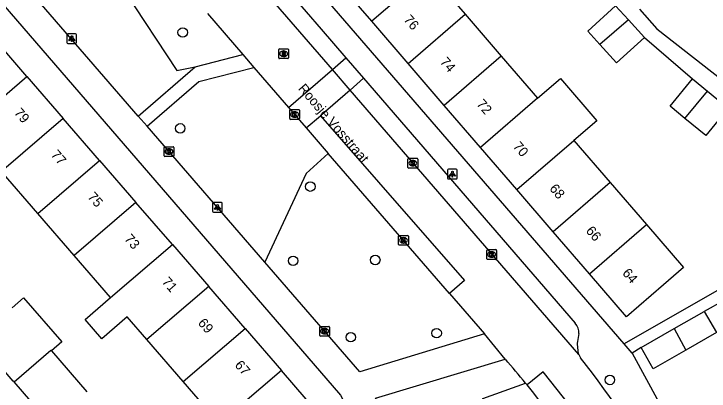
# Model space of a CAD drawing. Extents: x 160304 to 160954, y 383686 to 384161.
# Drawn here: x 160603.5 to 160674.9, y 383939.6 to 383978.2 of the extents above; entities that cross this region are included whole.
import ezdxf

# ---------------------------------------------------------------- set-up
doc = ezdxf.new("R2010")
doc.units = 0
for name, color, linetype in [('IMGEO_Boom', 7, 'Continuous'), ('IMGEO_Groenvoorziening', 7, 'Continuous'), ('IMGEO_Kolk', 7, 'Continuous'), ('IMGEO_Lichtpunt', 7, 'Continuous'), ('IMGEO_Openbare_ruimte_label', 7, 'Continuous'), ('IMGEO_Pand', 7, 'Continuous'), ('IMGEO_Pand_nummerreeks', 7, 'Continuous'), ('IMGEO_Parkeervlak_open', 7, 'Continuous'), ('IMGEO_Rijbaan_lokaal_open', 7, 'Continuous'), ('IMGEO_Rioolput', 7, 'Continuous'), ('IMGEO_Voetpad_open', 7, 'Continuous')]:
    doc.layers.add(name, color=color, linetype=linetype)

msp = doc.modelspace()

# ---------------------------------------------------------------- linework, layer by layer
at = {"layer": 'IMGEO_Boom'}
for centre in [(160620.841, 383976.338), (160620.586, 383966.501), (160633.933, 383960.53), (160632.169, 383952.919), (160640.598, 383953.001), (160646.895, 383945.495), (160638.087, 383945.081), (160664.674, 383940.697)]:
    msp.add_circle(centre, 0.489, dxfattribs=at)
at = {"layer": 'IMGEO_Groenvoorziening'}
for points in [[(160613.422, 383989.772), (160610.309, 383986.182), (160614.865, 383980.618), (160620.248, 383972.445), (160622.102, 383972.826)], [(160635.78, 383963.935), (160633.522, 383961.858), (160629.26, 383952.781)], [(160667.2, 383923.012), (160658.953, 383920.96), (160657.989, 383920.86), (160657.227, 383921.053), (160656.563, 383921.472), (160656.06, 383922.076), (160650.385, 383929.86), (160651.645, 383938.783), (160656.021, 383940.378)]]:
    msp.add_lwpolyline(points, dxfattribs=at)
at = {"layer": 'IMGEO_Kolk'}
for p, q in [((160631.822, 383967.502), (160631.822, 383968.354)), ((160631.897, 383968.428), (160632.749, 383968.428)), ((160632.31, 383968.208), (160632.335, 383968.208)), ((160632.823, 383968.354), (160632.823, 383967.502)), ((160632.749, 383967.428), (160631.897, 383967.428)), ((160632.333, 383967.648), (160632.308, 383967.648)), ((160618.929, 383963.696), (160618.929, 383964.548)), ((160619.004, 383964.622), (160619.856, 383964.622)), ((160619.93, 383964.548), (160619.93, 383963.696)), ((160619.44, 383963.842), (160619.415, 383963.842)), ((160619.417, 383964.402), (160619.442, 383964.402)), ((160619.856, 383963.622), (160619.004, 383963.622)), ((160643.955, 383962.505), (160643.955, 383963.357)), ((160644.03, 383963.431), (160644.882, 383963.431)), ((160644.443, 383963.211), (160644.468, 383963.211)), ((160644.956, 383963.357), (160644.956, 383962.505)), ((160644.882, 383962.431), (160644.03, 383962.431)), ((160644.466, 383962.651), (160644.441, 383962.651)), ((160642.993, 383954.592), (160642.993, 383955.444)), ((160643.068, 383955.518), (160643.92, 383955.518)), ((160643.481, 383955.298), (160643.506, 383955.298)), ((160643.994, 383955.444), (160643.994, 383954.592)), ((160643.92, 383954.518), (160643.068, 383954.518)), ((160643.504, 383954.738), (160643.479, 383954.738)), ((160652.044, 383953.135), (160652.044, 383953.987)), ((160652.119, 383954.061), (160652.971, 383954.061)), ((160652.532, 383953.841), (160652.557, 383953.841)), ((160653.045, 383953.987), (160653.045, 383953.135)), ((160652.971, 383953.061), (160652.119, 383953.061)), ((160652.555, 383953.281), (160652.53, 383953.281)), ((160634.904, 383945.265), (160634.904, 383946.117)), ((160634.979, 383946.191), (160635.831, 383946.191)), ((160635.392, 383945.971), (160635.417, 383945.971)), ((160635.905, 383946.117), (160635.905, 383945.265)), ((160635.831, 383945.191), (160634.979, 383945.191)), ((160635.415, 383945.411), (160635.39, 383945.411))]:
    msp.add_line(p, q, dxfattribs=at)
for points in [[(160631.822, 383967.502), (160631.822, 383968.354)], [(160631.897, 383968.428), (160632.749, 383968.428)], [(160632.143, 383968.128), (160632.266, 383968.128), (160632.266, 383967.977), (160632.396, 383968.128), (160632.56, 383968.128), (160632.414, 383967.977), (160632.567, 383967.728), (160632.415, 383967.728), (160632.33, 383967.892), (160632.266, 383967.825), (160632.266, 383967.728), (160632.143, 383967.728), (160632.143, 383968.128)], [(160632.823, 383968.354), (160632.823, 383967.502)], [(160632.749, 383967.428), (160631.897, 383967.428)], [(160618.929, 383963.696), (160618.929, 383964.548)], [(160619.004, 383964.622), (160619.856, 383964.622)], [(160619.93, 383964.548), (160619.93, 383963.696)], [(160619.25, 383964.322), (160619.373, 383964.322), (160619.373, 383964.171), (160619.503, 383964.322), (160619.667, 383964.322), (160619.521, 383964.171), (160619.674, 383963.922), (160619.522, 383963.922), (160619.437, 383964.086), (160619.373, 383964.019), (160619.373, 383963.922), (160619.25, 383963.922), (160619.25, 383964.322)], [(160619.856, 383963.622), (160619.004, 383963.622)], [(160643.955, 383962.505), (160643.955, 383963.357)], [(160644.03, 383963.431), (160644.882, 383963.431)], [(160644.276, 383963.131), (160644.399, 383963.131), (160644.399, 383962.98), (160644.529, 383963.131), (160644.693, 383963.131), (160644.547, 383962.98), (160644.7, 383962.731), (160644.548, 383962.731), (160644.463, 383962.895), (160644.399, 383962.828), (160644.399, 383962.731), (160644.276, 383962.731), (160644.276, 383963.131)], [(160644.956, 383963.357), (160644.956, 383962.505)], [(160644.882, 383962.431), (160644.03, 383962.431)], [(160642.993, 383954.592), (160642.993, 383955.444)], [(160643.068, 383955.518), (160643.92, 383955.518)], [(160643.314, 383955.218), (160643.437, 383955.218), (160643.437, 383955.067), (160643.567, 383955.218), (160643.731, 383955.218), (160643.585, 383955.067), (160643.738, 383954.818), (160643.586, 383954.818), (160643.501, 383954.982), (160643.437, 383954.915), (160643.437, 383954.818), (160643.314, 383954.818), (160643.314, 383955.218)], [(160643.994, 383955.444), (160643.994, 383954.592)], [(160643.92, 383954.518), (160643.068, 383954.518)], [(160652.044, 383953.135), (160652.044, 383953.987)], [(160652.119, 383954.061), (160652.971, 383954.061)], [(160652.365, 383953.761), (160652.488, 383953.761), (160652.488, 383953.61), (160652.618, 383953.761), (160652.782, 383953.761), (160652.636, 383953.61), (160652.789, 383953.361), (160652.637, 383953.361), (160652.552, 383953.525), (160652.488, 383953.458), (160652.488, 383953.361), (160652.365, 383953.361), (160652.365, 383953.761)], [(160653.045, 383953.987), (160653.045, 383953.135)], [(160652.971, 383953.061), (160652.119, 383953.061)], [(160634.904, 383945.265), (160634.904, 383946.117)], [(160634.979, 383946.191), (160635.831, 383946.191)], [(160635.225, 383945.891), (160635.348, 383945.891), (160635.348, 383945.74), (160635.478, 383945.891), (160635.642, 383945.891), (160635.496, 383945.74), (160635.649, 383945.491), (160635.497, 383945.491), (160635.412, 383945.655), (160635.348, 383945.588), (160635.348, 383945.491), (160635.225, 383945.491), (160635.225, 383945.891)], [(160635.905, 383946.117), (160635.905, 383945.265)], [(160635.831, 383945.191), (160634.979, 383945.191)]]:
    msp.add_lwpolyline(points, dxfattribs=at)
for centre, start, end in [((160631.899, 383968.352), 91.55205, 178.44795), ((160631.899, 383968.352), 91.55205, 178.44795), ((160632.747, 383968.352), 1.55205, 88.44795), ((160632.747, 383968.352), 1.55205, 88.44795), ((160631.899, 383967.504), 181.55205, 268.44795), ((160631.899, 383967.504), 181.55205, 268.44795), ((160632.747, 383967.504), 271.55205, 358.44795), ((160632.747, 383967.504), 271.55205, 358.44795), ((160619.006, 383964.546), 91.55205, 178.44795), ((160619.006, 383964.546), 91.55205, 178.44795), ((160619.854, 383964.546), 1.55205, 88.44795), ((160619.854, 383964.546), 1.55205, 88.44795), ((160619.006, 383963.698), 181.55205, 268.44795), ((160619.006, 383963.698), 181.55205, 268.44795), ((160619.854, 383963.698), 271.55205, 358.44795), ((160619.854, 383963.698), 271.55205, 358.44795), ((160644.032, 383963.355), 91.55205, 178.44795), ((160644.032, 383963.355), 91.55205, 178.44795), ((160644.88, 383963.355), 1.55205, 88.44795), ((160644.88, 383963.355), 1.55205, 88.44795), ((160644.032, 383962.507), 181.55205, 268.44795), ((160644.032, 383962.507), 181.55205, 268.44795), ((160644.88, 383962.507), 271.55205, 358.44795), ((160644.88, 383962.507), 271.55205, 358.44795), ((160643.07, 383955.442), 91.55205, 178.44795), ((160643.07, 383955.442), 91.55205, 178.44795), ((160643.918, 383955.442), 1.55205, 88.44795), ((160643.918, 383955.442), 1.55205, 88.44795), ((160643.07, 383954.594), 181.55205, 268.44795), ((160643.07, 383954.594), 181.55205, 268.44795), ((160643.918, 383954.594), 271.55205, 358.44795), ((160643.918, 383954.594), 271.55205, 358.44795), ((160652.121, 383953.985), 91.55205, 178.44795), ((160652.121, 383953.985), 91.55205, 178.44795), ((160652.969, 383953.985), 1.55205, 88.44795), ((160652.969, 383953.985), 1.55205, 88.44795), ((160652.121, 383953.137), 181.55205, 268.44795), ((160652.121, 383953.137), 181.55205, 268.44795), ((160652.969, 383953.137), 271.55205, 358.44795), ((160652.969, 383953.137), 271.55205, 358.44795), ((160634.981, 383946.115), 91.55205, 178.44795), ((160634.981, 383946.115), 91.55205, 178.44795), ((160635.829, 383946.115), 1.55205, 88.44795), ((160635.829, 383946.115), 1.55205, 88.44795), ((160634.981, 383945.267), 181.55205, 268.44795), ((160634.981, 383945.267), 181.55205, 268.44795), ((160635.829, 383945.267), 271.55205, 358.44795), ((160635.829, 383945.267), 271.55205, 358.44795)]:
    msp.add_arc(centre, 0.0765, start, end, dxfattribs=at)
for centre, major_axis, ratio, start_param, end_param in [((160632.309, 383967.928), (-0.387, 0.002), 0.722429, 4.712389, 7.853982), ((160632.334, 383967.928), (-0.39, 0.002), 0.717154, 1.570796, 4.712389), ((160619.416, 383964.122), (-0.387, 0.002), 0.722429, 4.712389, 7.853982), ((160619.441, 383964.122), (-0.39, 0.002), 0.717154, 1.570796, 4.712389), ((160644.442, 383962.931), (-0.387, 0.002), 0.722429, 4.712389, 7.853982), ((160644.467, 383962.931), (-0.39, 0.002), 0.717154, 1.570796, 4.712389), ((160643.48, 383955.018), (-0.387, 0.002), 0.722429, 4.712389, 7.853982), ((160643.505, 383955.018), (-0.39, 0.002), 0.717154, 1.570796, 4.712389), ((160652.531, 383953.561), (-0.387, 0.002), 0.722429, 4.712389, 7.853982), ((160652.556, 383953.561), (-0.39, 0.002), 0.717154, 1.570796, 4.712389), ((160635.391, 383945.691), (-0.387, 0.002), 0.722429, 4.712389, 7.853982), ((160635.416, 383945.691), (-0.39, 0.002), 0.717154, 1.570796, 4.712389)]:
    msp.add_ellipse(centre, major_axis=major_axis, ratio=ratio, start_param=start_param, end_param=end_param, dxfattribs=at)
at = {"layer": 'IMGEO_Lichtpunt'}
for p, q in [((160608.953, 383976.11), (160608.953, 383975.303)), ((160608.953, 383976.11), (160608.953, 383975.303)), ((160609.855, 383976.205), (160609.047, 383976.205)), ((160609.855, 383976.205), (160609.047, 383976.205)), ((160609.949, 383975.303), (160609.949, 383976.11)), ((160609.949, 383975.303), (160609.949, 383976.11)), ((160609.047, 383975.209), (160609.855, 383975.209)), ((160609.047, 383975.209), (160609.855, 383975.209)), ((160648.912, 383962.309), (160648.104, 383962.309)), ((160648.912, 383962.309), (160648.104, 383962.309)), ((160648.01, 383962.214), (160648.01, 383961.407)), ((160648.01, 383962.214), (160648.01, 383961.407)), ((160649.006, 383961.407), (160649.006, 383962.214)), ((160649.006, 383961.407), (160649.006, 383962.214)), ((160648.104, 383961.313), (160648.912, 383961.313)), ((160648.104, 383961.313), (160648.912, 383961.313)), ((160623.907, 383958.801), (160623.907, 383957.994)), ((160623.907, 383958.801), (160623.907, 383957.994)), ((160624.809, 383958.896), (160624.001, 383958.896)), ((160624.809, 383958.896), (160624.001, 383958.896)), ((160624.903, 383957.994), (160624.903, 383958.801)), ((160624.903, 383957.994), (160624.903, 383958.801)), ((160624.001, 383957.9), (160624.809, 383957.9)), ((160624.001, 383957.9), (160624.809, 383957.9))]:
    msp.add_line(p, q, dxfattribs=at)
for points in [[(160609.327, 383975.774), (160609.366, 383975.746), (160609.178, 383975.484), (160609.14, 383975.511), (160609.327, 383975.774)], [(160609.429, 383975.726), (160609.476, 383975.726), (160609.476, 383975.404), (160609.429, 383975.404), (160609.429, 383975.726)], [(160609.539, 383975.746), (160609.577, 383975.773), (160609.764, 383975.511), (160609.725, 383975.483), (160609.539, 383975.746)], [(160648.384, 383961.878), (160648.423, 383961.85), (160648.235, 383961.588), (160648.197, 383961.615), (160648.384, 383961.878)], [(160648.486, 383961.83), (160648.533, 383961.83), (160648.533, 383961.508), (160648.486, 383961.508), (160648.486, 383961.83)], [(160648.596, 383961.85), (160648.634, 383961.877), (160648.821, 383961.615), (160648.782, 383961.587), (160648.596, 383961.85)], [(160624.281, 383958.465), (160624.32, 383958.437), (160624.132, 383958.175), (160624.094, 383958.202), (160624.281, 383958.465)], [(160624.383, 383958.417), (160624.43, 383958.417), (160624.43, 383958.095), (160624.383, 383958.095), (160624.383, 383958.417)], [(160624.493, 383958.437), (160624.531, 383958.464), (160624.718, 383958.202), (160624.679, 383958.174), (160624.493, 383958.437)]]:
    msp.add_lwpolyline(points, dxfattribs=at)
for centre in [(160609.452, 383975.908), (160648.509, 383962.012), (160624.406, 383958.599)]:
    msp.add_circle(centre, 0.0994, dxfattribs=at)
for centre, start, end in [((160609.047, 383976.11), 90, 180), ((160609.047, 383976.11), 90, 180), ((160609.855, 383976.11), 0, 90), ((160609.855, 383976.11), 0, 90), ((160609.047, 383975.303), 180, 270), ((160609.047, 383975.303), 180, 270), ((160609.855, 383975.303), 270, 0), ((160609.855, 383975.303), 270, 360), ((160648.104, 383962.214), 90, 180), ((160648.104, 383962.214), 90, 180), ((160648.912, 383962.214), 0, 90), ((160648.912, 383962.214), 0, 90), ((160648.104, 383961.407), 180, 270), ((160648.104, 383961.407), 180, 270), ((160648.912, 383961.407), 270, 0), ((160648.912, 383961.407), 270, 360), ((160624.001, 383958.801), 90, 180), ((160624.001, 383958.801), 90, 180), ((160624.809, 383958.801), 0, 90), ((160624.809, 383958.801), 0, 90), ((160624.001, 383957.994), 180, 270), ((160624.001, 383957.994), 180, 270), ((160624.809, 383957.994), 270, 0), ((160624.809, 383957.994), 270, 360)]:
    msp.add_arc(centre, 0.0946, start, end, dxfattribs=at)
at = {"layer": 'IMGEO_Pand'}
for points in [[(160646.083, 383982.531), (160640.235, 383977.484)], [(160646.083, 383982.531), (160649.808, 383978.215)], [(160640.235, 383977.484), (160636.509, 383981.8)], [(160663.651, 383975.103), (160662.402, 383976.477), (160665.256, 383979.071)], [(160665.256, 383979.071), (160666.572, 383977.624)], [(160643.961, 383973.168), (160649.808, 383978.215)], [(160649.808, 383978.215), (160653.533, 383973.9)], [(160643.961, 383973.168), (160640.235, 383977.484)], [(160666.572, 383977.624), (160663.651, 383975.103)], [(160666.572, 383977.624), (160668.22, 383975.811)], [(160604.854, 383971.83), (160601.124, 383976.14)], [(160668.22, 383975.811), (160665.366, 383973.216), (160663.651, 383975.103)], [(160653.533, 383973.9), (160647.686, 383968.853)], [(160653.533, 383973.9), (160657.259, 383969.584)], [(160647.686, 383968.853), (160643.961, 383973.168)], [(160598.52, 383966.37), (160604.854, 383971.83)], [(160604.854, 383971.83), (160608.58, 383967.526)], [(160657.259, 383969.584), (160659.595, 383971.601), (160663.321, 383967.284), (160660.985, 383965.267)], [(160672.381, 383967.517), (160670.848, 383968.768), (160673.14, 383971.579)], [(160673.14, 383971.579), (160674.702, 383970.304)], [(160672.381, 383967.517), (160674.702, 383970.304)], [(160674.702, 383970.304), (160676.813, 383968.584)], [(160657.259, 383969.584), (160651.412, 383964.536)], [(160651.412, 383964.536), (160647.686, 383968.853)], [(160676.813, 383968.584), (160674.521, 383965.773), (160672.381, 383967.517)], [(160608.58, 383967.526), (160602.252, 383962.062)], [(160612.311, 383963.216), (160608.58, 383967.526)], [(160655.138, 383960.22), (160660.985, 383965.267)], [(160660.985, 383965.267), (160664.711, 383960.952)], [(160655.138, 383960.22), (160651.412, 383964.536)], [(160605.98, 383957.759), (160612.311, 383963.216)], [(160612.311, 383963.216), (160616.036, 383958.913)], [(160605.98, 383957.759), (160602.252, 383962.062)], [(160664.711, 383960.952), (160658.864, 383955.904)], [(160664.711, 383960.952), (160668.436, 383956.636)], [(160658.864, 383955.904), (160655.138, 383960.22)], [(160616.036, 383958.913), (160609.707, 383953.456)], [(160619.776, 383954.593), (160616.036, 383958.913)], [(160609.707, 383953.456), (160605.98, 383957.759)], [(160668.436, 383956.636), (160672.24, 383952.23), (160670.178, 383950.451), (160666.393, 383947.183), (160662.59, 383951.589)], [(160662.59, 383951.589), (160668.436, 383956.636)], [(160662.59, 383951.589), (160658.864, 383955.904)], [(160613.435, 383949.153), (160619.776, 383954.593)], [(160619.776, 383954.593), (160623.509, 383950.28)], [(160613.435, 383949.153), (160609.707, 383953.456)], [(160623.509, 383950.28), (160617.164, 383944.849)], [(160627.234, 383945.977), (160623.509, 383950.28)], [(160603.336, 383948.097), (160604.517, 383949.12), (160608.426, 383944.604), (160607.365, 383943.686)], [(160617.164, 383944.849), (160615.145, 383947.18), (160612.543, 383944.926), (160610.833, 383946.899), (160613.435, 383949.153)], [(160671.276, 383945.963), (160674.363, 383947.727)], [(160674.363, 383947.727), (160675.604, 383945.557), (160672.453, 383943.756)], [(160620.895, 383940.542), (160627.234, 383945.977)], [(160627.234, 383945.977), (160630.965, 383941.666)], [(160667.877, 383944.02), (160671.276, 383945.963)], [(160671.276, 383945.963), (160672.453, 383943.756)], [(160603.531, 383940.497), (160603.452, 383940.588), (160599.728, 383944.89)], [(160620.895, 383940.542), (160617.164, 383944.849)], [(160603.531, 383940.497), (160607.301, 383943.761), (160607.365, 383943.686)], [(160672.453, 383943.756), (160669.118, 383941.85), (160667.877, 383944.02)], [(160607.365, 383943.686), (160611.004, 383939.482)], [(160630.965, 383941.666), (160624.623, 383936.239)], [(160628.454, 383931.789), (160631.011, 383933.975), (160634.791, 383937.247), (160630.965, 383941.666)], [(160607.169, 383936.294), (160603.531, 383940.497)], [(160624.623, 383936.239), (160620.895, 383940.542)]]:
    msp.add_lwpolyline(points, dxfattribs=at)
at = {"layer": 'IMGEO_Parkeervlak_open'}
for points in [[(160636.197, 383972.526), (160637.593, 383973.734)], [(160639.405, 383971.639), (160638.009, 383970.431)], [(160633.52, 383966.546), (160635.78, 383963.935)], [(160648.205, 383949.577), (160635.78, 383963.935)]]:
    msp.add_lwpolyline(points, dxfattribs=at)
msp.add_arc((160589.968, 383886.5), 85.239, 29.58808, 39.03899, dxfattribs=at)
at = {"layer": 'IMGEO_Rijbaan_lokaal_open'}
for points in [[(160636.197, 383972.526), (160619.444, 383991.902)], [(160623.377, 383978.267), (160626.995, 383974.086)], [(160626.995, 383974.086), (160628.155, 383972.746)], [(160628.155, 383972.746), (160631.707, 383968.641)], [(160631.707, 383968.641), (160636.197, 383972.526)], [(160638.009, 383970.431), (160636.197, 383972.526)], [(160638.009, 383970.431), (160634.971, 383967.802)], [(160661.474, 383943.291), (160638.009, 383970.431)], [(160631.707, 383968.641), (160633.52, 383966.546)], [(160633.52, 383966.546), (160634.971, 383967.802)], [(160634.971, 383967.802), (160640.947, 383960.968), (160649.767, 383950.885), (160648.205, 383949.577)], [(160648.205, 383949.577), (160651.803, 383945.418)], [(160653.945, 383942.828), (160651.803, 383945.418)], [(160661.474, 383943.291), (160661.66, 383942.977)], [(160666.921, 383927.796), (160660.678, 383937.933), (160659.925, 383938.885), (160657.825, 383941.542), (160656.175, 383940.188)], [(160656.175, 383940.188), (160656.021, 383940.378)]]:
    msp.add_lwpolyline(points, dxfattribs=at)
for centre, radius, start, end in [((160592.028, 383888.258), 82.533, 39.16144, 41.39091), ((160588.303, 383885.017), 93.491, 28.55214, 38.31252)]:
    msp.add_arc(centre, radius, start, end, dxfattribs=at)
at = {"layer": 'IMGEO_Rioolput'}
for p, q in [((160630.693, 383973.734), (160630.693, 383974.586)), ((160630.768, 383974.66), (160631.62, 383974.66)), ((160631.181, 383974.44), (160631.206, 383974.44)), ((160631.694, 383974.586), (160631.694, 383973.734)), ((160631.204, 383973.88), (160631.179, 383973.88)), ((160631.62, 383973.66), (160630.768, 383973.66))]:
    msp.add_line(p, q, dxfattribs=at)
for points in [[(160630.693, 383973.734), (160630.693, 383974.586)], [(160630.768, 383974.66), (160631.62, 383974.66)], [(160631.694, 383974.586), (160631.694, 383973.734)], [(160631.282, 383974.358), (160631.03, 383974.36), (160631.03, 383973.96)], [(160631.03, 383973.96), (160631.154, 383973.96), (160631.154, 383974.122), (160631.165, 383974.122)], [(160631.208, 383974.279), (160631.154, 383974.279), (160631.154, 383974.198)], [(160631.154, 383974.198), (160631.206, 383974.198)], [(160631.212, 383974.093), (160631.283, 383973.96), (160631.423, 383973.96), (160631.358, 383974.086)], [(160631.62, 383973.66), (160630.768, 383973.66)]]:
    msp.add_lwpolyline(points, dxfattribs=at)
for centre, radius, start, end in [((160630.77, 383974.584), 0.0765, 91.55205, 178.44795), ((160630.77, 383974.584), 0.0765, 91.55205, 178.44795), ((160631.618, 383974.584), 0.0765, 1.55205, 88.44795), ((160631.618, 383974.584), 0.0765, 1.55205, 88.44795), ((160630.77, 383973.736), 0.0765, 181.55205, 268.44795), ((160630.77, 383973.736), 0.0765, 181.55205, 268.44795), ((160631.164, 383974.069), 0.0533, 26.02933, 88.69889), ((160631.19, 383974.387), 0.19, 274.7715, 282.96867), ((160631.214, 383974.183), 0.0964, 77.00612, 93.18647), ((160631.228, 383974.24), 0.0378, 276.66336, 79.67722), ((160631.281, 383974.248), 0.109, 350.36119, 89.41601), ((160631.279, 383974.248), 0.112, 277.58423, 350.98172), ((160631.263, 383974.033), 0.108, 29.51342, 73.79051), ((160631.618, 383973.736), 0.0765, 271.55205, 358.44795), ((160631.618, 383973.736), 0.0765, 271.55205, 358.44795)]:
    msp.add_arc(centre, radius, start, end, dxfattribs=at)
for centre, major_axis, ratio, start_param, end_param in [((160631.18, 383974.16), (-0.387, 0.002), 0.722429, 4.712389, 7.853982), ((160631.205, 383974.16), (-0.39, 0.002), 0.717154, 1.570796, 4.712389)]:
    msp.add_ellipse(centre, major_axis=major_axis, ratio=ratio, start_param=start_param, end_param=end_param, dxfattribs=at)
at = {"layer": 'IMGEO_Voetpad_open'}
for points in [[(160616.269, 383967.769), (160601.248, 383985.099), (160609.035, 383994.079)], [(160666.156, 383944.39), (160623.685, 383993.483)], [(160622.749, 383990.925), (160635.052, 383976.673), (160637.593, 383973.734)], [(160667.71, 383978.714), (160669.487, 383976.727), (160681.857, 383967.052), (160690.402, 383960.141), (160692.419, 383959.507), (160709.672, 383969.859), (160723.45, 383977.91), (160723.634, 383978.018), (160720.824, 383982.828), (160726.65, 383986.232)], [(160599.096, 383983.036), (160637.034, 383939.15), (160638.073, 383937.196)], [(160668.22, 383975.811), (160673.14, 383971.579)], [(160622.102, 383972.826), (160626.995, 383974.086)], [(160637.593, 383973.734), (160639.405, 383971.639)], [(160616.269, 383967.769), (160622.102, 383972.826)], [(160617.179, 383966.719), (160622.503, 383971.317), (160628.155, 383972.746)], [(160639.405, 383971.639), (160661.127, 383946.517)], [(160676.813, 383968.584), (160684.239, 383962.534), (160689.847, 383957.964), (160688.992, 383957.451), (160666.156, 383944.39)], [(160617.179, 383966.719), (160616.269, 383967.769)], [(160629.26, 383952.781), (160617.179, 383966.719)], [(160651.803, 383945.418), (160639.023, 383941.517), (160629.26, 383952.781)], [(160676.446, 383948.887), (160674.363, 383947.727)], [(160661.481, 383945.463), (160661.341, 383944.625)], [(160666.961, 383943.459), (160666.156, 383944.39)], [(160667.877, 383944.02), (160666.961, 383943.459)], [(160666.961, 383943.459), (160673.507, 383931.437)], [(160655.348, 383911.26), (160640.639, 383938.82), (160653.945, 383942.828)]]:
    msp.add_lwpolyline(points, dxfattribs=at)
for centre, radius, start, end in [((160660.009, 383945.555), 1.475, 356.422, 40.70863), ((160665.384, 383944.354), 4.052, 176.17265, 195.21451)]:
    msp.add_arc(centre, radius, start, end, dxfattribs=at)

# ---------------------------------------------------------------- texts
at = {"layer": 'IMGEO_Openbare_ruimte_label'}
msp.add_text('Roosje Vosstraat', height=1, rotation=310.86241, dxfattribs=at).set_placement((160632.623, 383970.546))
at = {"layer": 'IMGEO_Pand_nummerreeks'}
for s, rotation, p in [('76', 310.80306, (160643.45, 383977.615)), ('74', 310.80306, (160647.19, 383973.283)), ('72', 310.80306, (160650.928, 383968.953)), ('79', 311.17991, (160603.476, 383968.062)), ('70', 310.80306, (160654.672, 383964.616)), ('77', 311.17827, (160607.25, 383963.748)), ('68', 310.80306, (160658.412, 383960.284)), ('75', 311.17991, (160611.024, 383959.434)), ('66', 310.80306, (160662.15, 383955.954)), ('73', 311.17991, (160614.797, 383955.121)), ('64', 310.80306, (160665.89, 383951.621)), ('71', 311.17991, (160618.646, 383950.722)), ('69', 311.17991, (160622.344, 383946.494)), ('67', 311.17991, (160626.118, 383942.18))]:
    msp.add_text(s, height=1, rotation=rotation, dxfattribs=at).set_placement(p)

doc.saveas('drawing.dxf')
